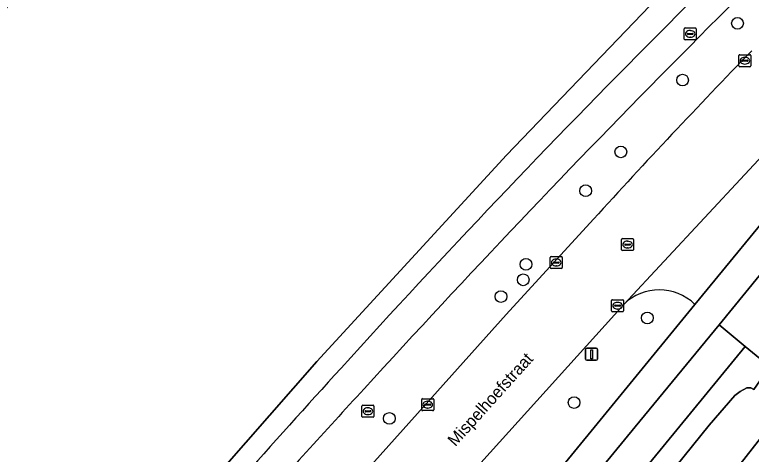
# Model space of a CAD drawing. Extents: x 156141 to 158132, y 385651 to 388333.
# Drawn here: x 156398 to 156459.3, y 386789.8 to 386826.5 of the extents above; entities that cross this region are included whole.
import ezdxf

# ---------------------------------------------------------------- set-up
doc = ezdxf.new("R2010")
doc.units = 0
for name, color, linetype in [('IMGEO_Berm_groen', 7, 'Continuous'), ('IMGEO_Boom', 7, 'Continuous'), ('IMGEO_Fietspad_gesloten', 7, 'Continuous'), ('IMGEO_Kolk', 7, 'Continuous'), ('IMGEO_Lichtmast', 7, 'Continuous'), ('IMGEO_Loofbos', 7, 'Continuous'), ('IMGEO_Oever', 7, 'Continuous'), ('IMGEO_Openbare_ruimte_label', 7, 'Continuous'), ('IMGEO_Rijbaan_lokaal_gesloten', 7, 'Continuous'), ('IMGEO_Rijbaan_lokaal_open', 7, 'Continuous'), ('IMGEO_Rioolput', 7, 'Continuous'), ('IMGEO_Waterloop', 7, 'Continuous')]:
    doc.layers.add(name, color=color, linetype=linetype)

msp = doc.modelspace()

# ---------------------------------------------------------------- linework, layer by layer
at = {"layer": 'IMGEO_Berm_groen'}
for points in [[(156417.462, 386784.626), (156419.746, 386782.581), (156421.757, 386784.808), (156422.964, 386783.706), (156427.936, 386789.222), (156438.907, 386801.482), (156446.182, 386809.429)], [(156448.688, 386802.316), (156425.65, 386776.766), (156430.32, 386772.58), (156454.622, 386802.315)], [(156458.809, 386798.806), (156456.645, 386800.618), (156449.641, 386792.109), (156415.127, 386750), (156407.451, 386740.66), (156406.186, 386739.074), (156405.777, 386738.372)], [(156410.971, 386740.449), (156413.097, 386742.97), (156418.817, 386750), (156458.809, 386798.806)]]:
    msp.add_lwpolyline(points, dxfattribs=at)
for centre, radius, start, end in [((157069.291, 386214.847), 865.567, 132.95264, 135.361886), ((156888.482, 386407.172), 597.863, 135.871216, 137.714527), ((157116.925, 386167.041), 933.051, 135.328269, 137.67668), ((156451.654, 386799.242), 4.272, 45.99851, 133.98218), ((156901.513, 386357.768), 645.378, 137.319417, 138.592727)]:
    msp.add_arc(centre, radius, start, end, dxfattribs=at)
at = {"layer": 'IMGEO_Boom'}
for centre in [(156458.169, 386825.75), (156453.594, 386821.013), (156448.451, 386815.029), (156445.523, 386811.788), (156440.548, 386805.648), (156440.321, 386804.361), (156438.462, 386802.965), (156450.656, 386801.181), (156444.558, 386794.128), (156429.169, 386792.802)]:
    msp.add_circle(centre, 0.489, dxfattribs=at)
at = {"layer": 'IMGEO_Fietspad_gesloten'}
for points in [[(156475.932, 386827.932), (156473.453, 386825.124), (156470.602, 386821.679), (156467.635, 386818.01), (156462.43, 386811.812), (156454.622, 386802.315), (156430.32, 386772.58), (156429.362, 386771.408), (156422.682, 386763.234), (156411.829, 386750), (156406.936, 386744.054), (156403.709, 386740.043), (156403.516, 386739.803), (156400.371, 386735.978), (156396.753, 386731.194)], [(156449.641, 386792.109), (156456.645, 386800.618), (156464.414, 386810.132), (156469.501, 386816.236), (156472.211, 386819.58), (156475.369, 386823.383), (156475.23, 386823.495), (156477.271, 386825.871)], [(156395.288, 386725), (156399.182, 386730.402), (156399.47, 386730.761), (156399.632, 386730.964), (156402.434, 386734.493), (156403.05, 386735.262), (156406.186, 386739.074), (156407.451, 386740.66), (156415.127, 386750), (156449.641, 386792.109)]]:
    msp.add_lwpolyline(points, dxfattribs=at)
for centre, radius, start, end in [((157123.713, 386159.175), 945.974, 132.985141, 135.281185), ((157069.291, 386214.847), 865.567, 132.95264, 135.361886), ((157014.454, 386263.794), 794.729, 135.098099, 137.860751), ((157116.925, 386167.041), 933.051, 135.328269, 137.67668), ((157132.525, 386153.241), 956.458, 137.69548, 139.23286), ((156901.513, 386357.768), 645.378, 137.319417, 138.592727)]:
    msp.add_arc(centre, radius, start, end, dxfattribs=at)
at = {"layer": 'IMGEO_Kolk'}
for p, q in [((156458.282, 386822.207), (156458.282, 386823.059)), ((156458.357, 386823.133), (156459.209, 386823.133)), ((156458.541, 386822.627), (156458.541, 386822.639)), ((156458.584, 386822.676), (156458.982, 386822.676)), ((156458.77, 386822.913), (156458.795, 386822.913)), ((156459.025, 386822.639), (156459.025, 386822.627)), ((156459.283, 386823.059), (156459.283, 386822.207)), ((156459.209, 386822.133), (156458.357, 386822.133)), ((156458.979, 386822.59), (156458.581, 386822.59)), ((156458.793, 386822.353), (156458.768, 386822.353)), ((156442.575, 386805.374), (156442.575, 386806.226)), ((156442.65, 386806.3), (156443.502, 386806.3)), ((156443.063, 386806.08), (156443.088, 386806.08)), ((156443.576, 386806.226), (156443.576, 386805.374)), ((156442.834, 386805.794), (156442.834, 386805.806)), ((156443.272, 386805.757), (156442.874, 386805.757)), ((156442.877, 386805.843), (156443.275, 386805.843)), ((156443.086, 386805.52), (156443.061, 386805.52)), ((156443.318, 386805.806), (156443.318, 386805.794)), ((156443.502, 386805.3), (156442.65, 386805.3)), ((156447.679, 386801.777), (156447.679, 386802.629)), ((156447.754, 386802.703), (156448.606, 386802.703)), ((156448.167, 386802.483), (156448.192, 386802.483)), ((156448.68, 386802.629), (156448.68, 386801.777)), ((156447.938, 386802.197), (156447.938, 386802.209)), ((156448.376, 386802.16), (156447.978, 386802.16)), ((156447.981, 386802.246), (156448.379, 386802.246)), ((156448.19, 386801.923), (156448.165, 386801.923)), ((156448.422, 386802.209), (156448.422, 386802.197)), ((156448.606, 386801.703), (156447.754, 386801.703)), ((156431.934, 386794.45), (156432.786, 386794.45)), ((156431.859, 386793.524), (156431.859, 386794.376)), ((156432.118, 386793.944), (156432.118, 386793.956)), ((156432.556, 386793.907), (156432.158, 386793.907)), ((156432.161, 386793.993), (156432.559, 386793.993)), ((156432.347, 386794.23), (156432.372, 386794.23)), ((156432.602, 386793.956), (156432.602, 386793.944)), ((156432.86, 386794.376), (156432.86, 386793.524)), ((156432.786, 386793.45), (156431.934, 386793.45)), ((156432.37, 386793.67), (156432.345, 386793.67))]:
    msp.add_line(p, q, dxfattribs=at)
for points in [[(156458.282, 386822.207), (156458.282, 386823.059)], [(156458.357, 386823.133), (156459.209, 386823.133)], [(156459.283, 386823.059), (156459.283, 386822.207)], [(156459.209, 386822.133), (156458.357, 386822.133)], [(156442.575, 386805.374), (156442.575, 386806.226)], [(156442.65, 386806.3), (156443.502, 386806.3)], [(156443.576, 386806.226), (156443.576, 386805.374)], [(156443.502, 386805.3), (156442.65, 386805.3)], [(156447.679, 386801.777), (156447.679, 386802.629)], [(156447.754, 386802.703), (156448.606, 386802.703)], [(156448.68, 386802.629), (156448.68, 386801.777)], [(156448.606, 386801.703), (156447.754, 386801.703)], [(156431.934, 386794.45), (156432.786, 386794.45)], [(156431.859, 386793.524), (156431.859, 386794.376)], [(156432.86, 386794.376), (156432.86, 386793.524)], [(156432.786, 386793.45), (156431.934, 386793.45)]]:
    msp.add_lwpolyline(points, dxfattribs=at)
for centre, radius, start, end in [((156458.359, 386823.057), 0.0765, 91.55205, 178.44795), ((156458.359, 386823.057), 0.0765, 91.55205, 178.44795), ((156458.581, 386822.636), 0.0403, 85.87752, 175.75265), ((156458.578, 386822.626), 0.0366, 178.93798, 274.71019), ((156458.982, 386822.633), 0.043, 264.86636, 352.45326), ((156458.986, 386822.638), 0.0386, 1.73085, 96.63898), ((156459.207, 386823.057), 0.0765, 1.55205, 88.44795), ((156459.207, 386823.057), 0.0765, 1.55205, 88.44795), ((156458.359, 386822.209), 0.0765, 181.55205, 268.44795), ((156458.359, 386822.209), 0.0765, 181.55205, 268.44795), ((156459.207, 386822.209), 0.0765, 271.55205, 358.44795), ((156459.207, 386822.209), 0.0765, 271.55205, 358.44795), ((156442.652, 386806.224), 0.0765, 91.55205, 178.44795), ((156442.652, 386806.224), 0.0765, 91.55205, 178.44795), ((156443.5, 386806.224), 0.0765, 1.55205, 88.44795), ((156443.5, 386806.224), 0.0765, 1.55205, 88.44795), ((156442.874, 386805.803), 0.0403, 85.87752, 175.75265), ((156442.871, 386805.793), 0.0366, 178.93798, 274.71019), ((156443.275, 386805.8), 0.043, 264.86636, 352.45326), ((156443.279, 386805.805), 0.0386, 1.73085, 96.63898), ((156442.652, 386805.376), 0.0765, 181.55205, 268.44795), ((156442.652, 386805.376), 0.0765, 181.55205, 268.44795), ((156443.5, 386805.376), 0.0765, 271.55205, 358.44795), ((156443.5, 386805.376), 0.0765, 271.55205, 358.44795), ((156447.756, 386802.627), 0.0765, 91.55205, 178.44795), ((156447.756, 386802.627), 0.0765, 91.55205, 178.44795), ((156448.604, 386802.627), 0.0765, 1.55205, 88.44795), ((156448.604, 386802.627), 0.0765, 1.55205, 88.44795), ((156447.756, 386801.779), 0.0765, 181.55205, 268.44795), ((156447.756, 386801.779), 0.0765, 181.55205, 268.44795), ((156447.978, 386802.206), 0.0403, 85.87752, 175.75265), ((156447.975, 386802.196), 0.0366, 178.93798, 274.71019), ((156448.379, 386802.203), 0.043, 264.86636, 352.45326), ((156448.383, 386802.208), 0.0386, 1.73085, 96.63898), ((156448.604, 386801.779), 0.0765, 271.55205, 358.44795), ((156448.604, 386801.779), 0.0765, 271.55205, 358.44795), ((156431.936, 386794.374), 0.0765, 91.55205, 178.44795), ((156431.936, 386794.374), 0.0765, 91.55205, 178.44795), ((156432.784, 386794.374), 0.0765, 1.55205, 88.44795), ((156432.784, 386794.374), 0.0765, 1.55205, 88.44795), ((156432.158, 386793.953), 0.0403, 85.87752, 175.75265), ((156432.155, 386793.943), 0.0366, 178.93798, 274.71019), ((156432.559, 386793.95), 0.043, 264.86636, 352.45326), ((156432.563, 386793.955), 0.0386, 1.73085, 96.63898), ((156431.936, 386793.526), 0.0765, 181.55205, 268.44795), ((156431.936, 386793.526), 0.0765, 181.55205, 268.44795), ((156432.784, 386793.526), 0.0765, 271.55205, 358.44795), ((156432.784, 386793.526), 0.0765, 271.55205, 358.44795)]:
    msp.add_arc(centre, radius, start, end, dxfattribs=at)
for centre, major_axis, ratio, start_param, end_param in [((156458.769, 386822.633), (-0.387, 0.002), 0.722429, 4.712389, 7.853982), ((156458.794, 386822.633), (-0.39, 0.002), 0.717154, 1.570796, 4.712389), ((156443.062, 386805.8), (-0.387, 0.002), 0.722429, 4.712389, 7.853982), ((156443.087, 386805.8), (-0.39, 0.002), 0.717154, 1.570796, 4.712389), ((156448.166, 386802.203), (-0.387, 0.002), 0.722429, 4.712389, 7.853982), ((156448.191, 386802.203), (-0.39, 0.002), 0.717154, 1.570796, 4.712389), ((156432.346, 386793.95), (-0.387, 0.002), 0.722429, 4.712389, 7.853982), ((156432.371, 386793.95), (-0.39, 0.002), 0.717154, 1.570796, 4.712389)]:
    msp.add_ellipse(centre, major_axis=major_axis, ratio=ratio, start_param=start_param, end_param=end_param, dxfattribs=at)
at = {"layer": 'IMGEO_Lichtmast'}
for p, q in [((156445.519, 386797.75), (156445.519, 386798.55)), ((156445.519, 386798.55), (156445.519, 386797.75)), ((156445.619, 386798.65), (156446.409, 386798.65)), ((156446.409, 386798.65), (156445.619, 386798.65)), ((156446.509, 386798.55), (156446.509, 386797.75)), ((156446.509, 386797.75), (156446.509, 386798.55)), ((156446.409, 386797.65), (156445.619, 386797.65)), ((156445.619, 386797.65), (156446.409, 386797.65))]:
    msp.add_line(p, q, dxfattribs=at)
msp.add_lwpolyline([(156445.939, 386798.525), (156446.089, 386798.525), (156446.089, 386797.775), (156445.939, 386797.775), (156445.939, 386798.525)], dxfattribs=at)
for centre, start, end in [((156445.619, 386798.55), 90, 180), ((156445.619, 386798.55), 90, 180), ((156446.409, 386798.55), 0, 90), ((156446.409, 386798.55), 360, 90), ((156445.619, 386797.75), 180, 270), ((156445.619, 386797.75), 180, 270), ((156446.409, 386797.75), 270, 0), ((156446.409, 386797.75), 270, 0)]:
    msp.add_arc(centre, 0.1, start, end, dxfattribs=at)
at = {"layer": 'IMGEO_Loofbos'}
msp.add_lwpolyline([(156373.627, 386738.284), (156377.846, 386743.729), (156378.025, 386743.673), (156392.935, 386762.089), (156409.337, 386781.78), (156423.12, 386797.547), (156438.936, 386814.747), (156453.514, 386829.977), (156432.819, 386847.005), (156425.59, 386841.259), (156421.139, 386837.721), (156419.963, 386839.201), (156416.851, 386843.116), (156414.088, 386846.592), (156411.901, 386849.597), (156383.603, 386806.033), (156345.942, 386750), (156319.44, 386711.006), (156328.204, 386706.015), (156336.412, 386700.768), (156340.458, 386698.073), (156352.908, 386693.536), (156356.441, 386698.274), (156368.107, 386728.082)], close=True, dxfattribs=at)
msp.add_lwpolyline([(156453.514, 386829.977), (156438.936, 386814.747), (156423.12, 386797.547), (156409.337, 386781.78), (156392.935, 386762.089), (156378.025, 386743.673), (156377.846, 386743.729), (156373.627, 386738.284), (156368.107, 386728.082), (156356.441, 386698.274), (156352.908, 386693.536), (156340.458, 386698.073), (156336.412, 386700.768), (156328.204, 386706.015), (156319.44, 386711.006), (156318.364, 386709.423), (156319.754, 386708.223), (156333.91, 386700.028), (156352.633, 386690.072), (156357.465, 386688.104), (156360.143, 386687.587), (156361.044, 386687.413), (156364.735, 386706.911)], dxfattribs=at)
for centre, radius, start, end in [((157123.713, 386159.175), 945.974, 132.985141, 135.281185), ((157014.454, 386263.794), 794.729, 135.098099, 137.860751), ((157132.525, 386153.241), 956.458, 137.69548, 139.23286)]:
    msp.add_arc(centre, radius, start, end, dxfattribs=at)
at = {"layer": 'IMGEO_Oever'}
for points in [[(156464.5, 386794.069), (156462.491, 386795.741), (156460.934, 386797.037), (156458.809, 386798.806), (156418.817, 386750), (156413.097, 386742.97), (156410.971, 386740.449)], [(156413.565, 386739.83), (156455.821, 386792.249), (156457.955, 386794.724), (156458.401, 386795.051), (156458.937, 386795.35), (156459.283, 386795.353), (156459.523, 386795.206), (156460.036, 386795.947), (156461.828, 386794.677), (156461.232, 386793.881), (156461.482, 386793.318), (156461.43, 386792.973), (156461.205, 386792.581), (156458.388, 386788.986), (156417.061, 386737.428)]]:
    msp.add_lwpolyline(points, dxfattribs=at)
at = {"layer": 'IMGEO_Rijbaan_lokaal_gesloten'}
for points in [[(156399.984, 386757.836), (156397.978, 386755.226), (156403.399, 386751.392), (156406.223, 386754.955), (156409.194, 386758.403), (156419.506, 386769.953), (156420.204, 386770.727), (156425.65, 386776.766), (156448.688, 386802.316), (156462.151, 386816.752), (156462.242, 386816.85), (156462.338, 386816.952), (156470.076, 386824.776), (156477.801, 386832.749), (156483.548, 386838.213), (156492.502, 386846.939)], [(156446.182, 386809.429), (156438.907, 386801.482), (156427.936, 386789.222), (156422.964, 386783.706), (156420.561, 386781.04), (156417.519, 386777.657), (156411.6, 386771.074), (156403.363, 386761.913)]]:
    msp.add_lwpolyline(points, dxfattribs=at)
msp.add_arc((156888.482, 386407.172), 597.863, 135.871216, 137.714527, dxfattribs=at)
at = {"layer": 'IMGEO_Rijbaan_lokaal_open'}
for points in [[(156462.151, 386816.752), (156448.688, 386802.316)], [(156454.622, 386802.315), (156462.43, 386811.812)]]:
    msp.add_lwpolyline(points, dxfattribs=at)
msp.add_lwpolyline([(156472.211, 386803.552), (156470.301, 386805.164), (156468.537, 386806.653), (156464.414, 386810.132), (156456.645, 386800.618), (156458.809, 386798.806), (156460.934, 386797.037), (156462.491, 386795.741), (156464.5, 386794.069)], close=True, dxfattribs=at)
msp.add_arc((156451.654, 386799.242), 4.272, 45.99851, 133.98218, dxfattribs=at)
at = {"layer": 'IMGEO_Rioolput'}
for p, q in [((156453.73, 386824.439), (156453.73, 386825.291)), ((156453.805, 386825.365), (156454.657, 386825.365)), ((156454.218, 386825.145), (156454.243, 386825.145)), ((156454.731, 386825.291), (156454.731, 386824.439)), ((156453.989, 386824.859), (156453.989, 386824.871)), ((156454.427, 386824.822), (156454.029, 386824.822)), ((156454.032, 386824.908), (156454.43, 386824.908)), ((156454.241, 386824.585), (156454.216, 386824.585)), ((156454.473, 386824.871), (156454.473, 386824.859)), ((156454.657, 386824.365), (156453.805, 386824.365)), ((156448.512, 386806.873), (156448.512, 386807.725)), ((156448.587, 386807.799), (156449.439, 386807.799)), ((156448.771, 386807.293), (156448.771, 386807.305)), ((156448.814, 386807.342), (156449.212, 386807.342)), ((156449, 386807.579), (156449.025, 386807.579)), ((156449.255, 386807.305), (156449.255, 386807.293)), ((156449.513, 386807.725), (156449.513, 386806.873)), ((156449.439, 386806.799), (156448.587, 386806.799)), ((156449.209, 386807.256), (156448.811, 386807.256)), ((156449.023, 386807.019), (156448.998, 386807.019)), ((156426.881, 386792.977), (156426.881, 386793.829)), ((156426.956, 386793.903), (156427.808, 386793.903)), ((156427.882, 386793.829), (156427.882, 386792.977)), ((156427.14, 386793.397), (156427.14, 386793.409)), ((156427.578, 386793.36), (156427.18, 386793.36)), ((156427.183, 386793.446), (156427.581, 386793.446)), ((156427.369, 386793.683), (156427.394, 386793.683)), ((156427.624, 386793.409), (156427.624, 386793.397)), ((156427.808, 386792.903), (156426.956, 386792.903)), ((156427.392, 386793.123), (156427.367, 386793.123))]:
    msp.add_line(p, q, dxfattribs=at)
for points in [[(156453.73, 386824.439), (156453.73, 386825.291)], [(156453.805, 386825.365), (156454.657, 386825.365)], [(156454.731, 386825.291), (156454.731, 386824.439)], [(156454.657, 386824.365), (156453.805, 386824.365)], [(156448.512, 386806.873), (156448.512, 386807.725)], [(156448.587, 386807.799), (156449.439, 386807.799)], [(156449.513, 386807.725), (156449.513, 386806.873)], [(156449.439, 386806.799), (156448.587, 386806.799)], [(156426.881, 386792.977), (156426.881, 386793.829)], [(156426.956, 386793.903), (156427.808, 386793.903)], [(156427.882, 386793.829), (156427.882, 386792.977)], [(156427.808, 386792.903), (156426.956, 386792.903)]]:
    msp.add_lwpolyline(points, dxfattribs=at)
for centre, radius, start, end in [((156453.807, 386825.289), 0.0765, 91.55205, 178.44795), ((156453.807, 386825.289), 0.0765, 91.55205, 178.44795), ((156454.655, 386825.289), 0.0765, 1.55205, 88.44795), ((156454.655, 386825.289), 0.0765, 1.55205, 88.44795), ((156454.029, 386824.868), 0.0403, 85.87752, 175.75265), ((156454.026, 386824.858), 0.0366, 178.93798, 274.71019), ((156454.43, 386824.865), 0.043, 264.86636, 352.45326), ((156454.434, 386824.87), 0.0386, 1.73085, 96.63898), ((156453.807, 386824.441), 0.0765, 181.55205, 268.44795), ((156453.807, 386824.441), 0.0765, 181.55205, 268.44795), ((156454.655, 386824.441), 0.0765, 271.55205, 358.44795), ((156454.655, 386824.441), 0.0765, 271.55205, 358.44795), ((156448.589, 386807.723), 0.0765, 91.55205, 178.44795), ((156448.589, 386807.723), 0.0765, 91.55205, 178.44795), ((156448.811, 386807.302), 0.0403, 85.87752, 175.75265), ((156448.808, 386807.292), 0.0366, 178.93798, 274.71019), ((156449.212, 386807.299), 0.043, 264.86636, 352.45326), ((156449.216, 386807.304), 0.0386, 1.73085, 96.63898), ((156449.437, 386807.723), 0.0765, 1.55205, 88.44795), ((156449.437, 386807.723), 0.0765, 1.55205, 88.44795), ((156448.589, 386806.875), 0.0765, 181.55205, 268.44795), ((156448.589, 386806.875), 0.0765, 181.55205, 268.44795), ((156449.437, 386806.875), 0.0765, 271.55205, 358.44795), ((156449.437, 386806.875), 0.0765, 271.55205, 358.44795), ((156426.958, 386793.827), 0.0765, 91.55205, 178.44795), ((156426.958, 386793.827), 0.0765, 91.55205, 178.44795), ((156427.806, 386793.827), 0.0765, 1.55205, 88.44795), ((156427.806, 386793.827), 0.0765, 1.55205, 88.44795), ((156427.18, 386793.406), 0.0403, 85.87752, 175.75265), ((156427.177, 386793.396), 0.0366, 178.93798, 274.71019), ((156427.581, 386793.403), 0.043, 264.86636, 352.45326), ((156427.585, 386793.408), 0.0386, 1.73085, 96.63898), ((156426.958, 386792.979), 0.0765, 181.55205, 268.44795), ((156426.958, 386792.979), 0.0765, 181.55205, 268.44795), ((156427.806, 386792.979), 0.0765, 271.55205, 358.44795), ((156427.806, 386792.979), 0.0765, 271.55205, 358.44795)]:
    msp.add_arc(centre, radius, start, end, dxfattribs=at)
for centre, major_axis, ratio, start_param, end_param in [((156454.217, 386824.865), (-0.387, 0.002), 0.722429, 4.712389, 7.853982), ((156454.242, 386824.865), (-0.39, 0.002), 0.717154, 1.570796, 4.712389), ((156448.999, 386807.299), (-0.387, 0.002), 0.722429, 4.712389, 7.853982), ((156449.024, 386807.299), (-0.39, 0.002), 0.717154, 1.570796, 4.712389), ((156427.368, 386793.403), (-0.387, 0.002), 0.722429, 4.712389, 7.853982), ((156427.393, 386793.403), (-0.39, 0.002), 0.717154, 1.570796, 4.712389)]:
    msp.add_ellipse(centre, major_axis=major_axis, ratio=ratio, start_param=start_param, end_param=end_param, dxfattribs=at)
at = {"layer": 'IMGEO_Waterloop'}
msp.add_lwpolyline([(156458.388, 386788.986), (156461.205, 386792.581), (156461.43, 386792.973), (156461.482, 386793.318), (156461.232, 386793.881), (156461.828, 386794.677), (156460.036, 386795.947), (156459.523, 386795.206), (156459.283, 386795.353), (156458.937, 386795.35), (156458.401, 386795.051), (156457.955, 386794.724), (156455.821, 386792.249), (156413.565, 386739.83)], dxfattribs=at)

# ---------------------------------------------------------------- texts
at = {"layer": 'IMGEO_Openbare_ruimte_label'}
msp.add_text('Mispelhoefstraat', height=1, rotation=48.08094, dxfattribs=at).set_placement((156434.665, 386790.408))

doc.saveas('drawing.dxf')
